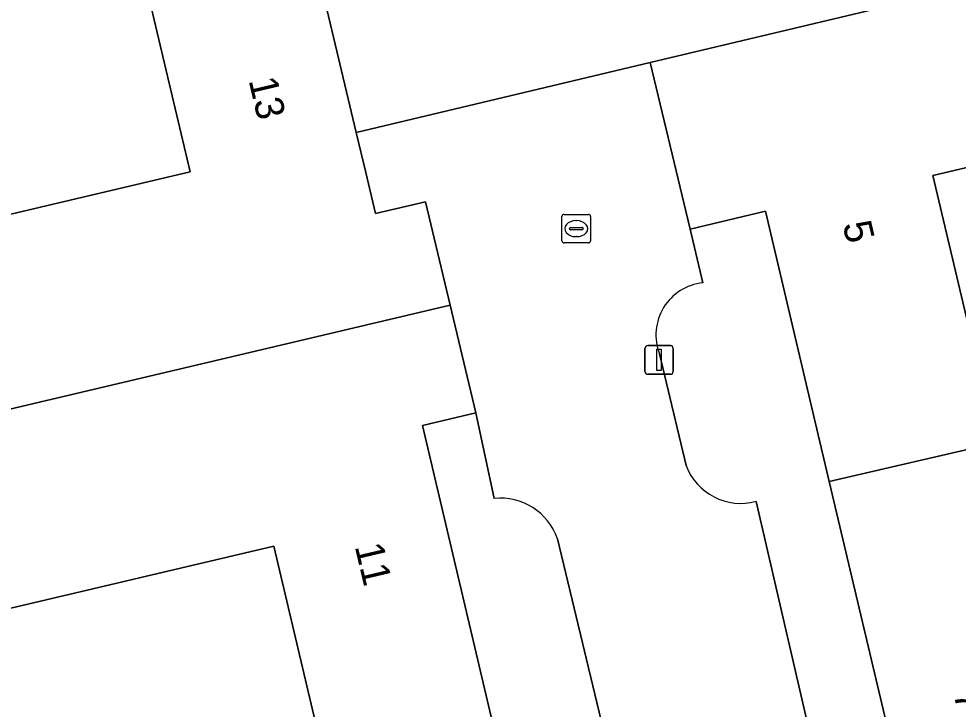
# Model space of a CAD drawing. Extents: x 157648 to 158502, y 379212 to 380938.
# Drawn here: x 158213.02 to 158245.9, y 380685.18 to 380709.33 of the extents above; entities that cross this region are included whole.
import ezdxf

# ---------------------------------------------------------------- set-up
doc = ezdxf.new("R2010")
doc.units = 0
for name, color, linetype in [('IMGEO_Erf', 7, 'Continuous'), ('IMGEO_Kolk', 7, 'Continuous'), ('IMGEO_Lichtmast', 7, 'Continuous'), ('IMGEO_Pand', 7, 'Continuous'), ('IMGEO_Pand_nummerreeks', 7, 'Continuous'), ('IMGEO_Rijbaan_lokaal_open', 7, 'Continuous')]:
    doc.layers.add(name, color=color, linetype=linetype)

msp = doc.modelspace()

# ---------------------------------------------------------------- linework, layer by layer
at = {"layer": 'IMGEO_Erf'}
for points in [[(158209.575, 380701.752), (158219.022, 380703.984), (158216.716, 380713.746)], [(158249.683, 380704.952), (158245.021, 380703.851), (158247.232, 380694.492)], [(158239.156, 380702.602), (158236.518, 380701.972), (158236.969, 380700.096)], [(158238.83, 380692.449), (158241.085, 380682.714), (158243.707, 380683.344), (158241.391, 380693.142), (158239.156, 380702.602)], [(158235.45, 380697.611), (158236.379, 380693.706)], [(158229.662, 380692.552), (158229.02, 380695.546), (158227.152, 380695.101), (158230.143, 380682.441), (158233.768, 380683.28), (158231.88, 380691.143)]]:
    msp.add_lwpolyline(points, dxfattribs=at)
msp.add_lwpolyline([(158212.334, 380688.613), (158202.676, 380686.331), (158204.989, 380676.546), (158216.449, 380679.193), (158224.26, 380681.102), (158221.948, 380690.885)], close=True, dxfattribs=at)
for centre, radius, start, end in [((158237.154, 380698.276), 1.829, 95.7962, 201.3316), ((158238.294, 380694.423), 2.045, 200.5122, 285.1856), ((158229.871, 380690.431), 2.131, 19.5142, 95.6337)]:
    msp.add_arc(centre, radius, start, end, dxfattribs=at)
at = {"layer": 'IMGEO_Kolk'}
for p, q in [((158232.036, 380701.565), (158232.036, 380702.417)), ((158232.111, 380702.491), (158232.963, 380702.491)), ((158232.524, 380702.271), (158232.549, 380702.271)), ((158233.037, 380702.417), (158233.037, 380701.565)), ((158232.295, 380701.985), (158232.295, 380701.997)), ((158232.733, 380701.948), (158232.335, 380701.948)), ((158232.338, 380702.034), (158232.736, 380702.034)), ((158232.779, 380701.997), (158232.779, 380701.985)), ((158232.547, 380701.711), (158232.522, 380701.711)), ((158232.963, 380701.491), (158232.111, 380701.491))]:
    msp.add_line(p, q, dxfattribs=at)
for points in [[(158232.036, 380701.565), (158232.036, 380702.417)], [(158232.111, 380702.491), (158232.963, 380702.491)], [(158233.037, 380702.417), (158233.037, 380701.565)], [(158232.963, 380701.491), (158232.111, 380701.491)]]:
    msp.add_lwpolyline(points, dxfattribs=at)
for centre, radius, start, end in [((158232.113, 380702.415), 0.0765, 91.552, 178.448), ((158232.113, 380702.415), 0.0765, 91.552, 178.448), ((158232.961, 380702.415), 0.0765, 1.552, 88.448), ((158232.961, 380702.415), 0.0765, 1.552, 88.448), ((158232.335, 380701.994), 0.0403, 85.8775, 175.7526), ((158232.332, 380701.984), 0.0366, 178.938, 274.7102), ((158232.736, 380701.991), 0.043, 264.8664, 352.4533), ((158232.74, 380701.996), 0.0386, 1.7309, 96.639), ((158232.113, 380701.567), 0.0765, 181.552, 268.448), ((158232.113, 380701.567), 0.0765, 181.552, 268.448), ((158232.961, 380701.567), 0.0765, 271.552, 358.448), ((158232.961, 380701.567), 0.0765, 271.552, 358.448)]:
    msp.add_arc(centre, radius, start, end, dxfattribs=at)
for centre, major_axis, ratio, start_param, end_param in [((158232.523, 380701.991), (-0.387, 0.002), 0.722429, 4.712389, 7.853982), ((158232.548, 380701.991), (-0.39, 0.002), 0.717154, 1.570796, 4.712389)]:
    msp.add_ellipse(centre, major_axis=major_axis, ratio=ratio, start_param=start_param, end_param=end_param, dxfattribs=at)
at = {"layer": 'IMGEO_Lichtmast'}
for p, q in [((158234.939, 380696.997), (158234.939, 380697.797)), ((158234.939, 380697.797), (158234.939, 380696.997)), ((158235.039, 380697.897), (158235.829, 380697.897)), ((158235.829, 380697.897), (158235.039, 380697.897)), ((158235.929, 380697.797), (158235.929, 380696.997)), ((158235.929, 380696.997), (158235.929, 380697.797)), ((158235.829, 380696.897), (158235.039, 380696.897)), ((158235.039, 380696.897), (158235.829, 380696.897))]:
    msp.add_line(p, q, dxfattribs=at)
msp.add_lwpolyline([(158235.359, 380697.772), (158235.509, 380697.772), (158235.509, 380697.022), (158235.359, 380697.022), (158235.359, 380697.772)], dxfattribs=at)
for centre, start, end in [((158235.039, 380697.797), 90, 180), ((158235.039, 380697.797), 90, 180), ((158235.829, 380697.797), 0, 90), ((158235.829, 380697.797), 360, 90), ((158235.039, 380696.997), 180, 270), ((158235.039, 380696.997), 180, 270), ((158235.829, 380696.997), 270, 0), ((158235.829, 380696.997), 270, 0)]:
    msp.add_arc(centre, 0.1, start, end, dxfattribs=at)
at = {"layer": 'IMGEO_Pand'}
for points in [[(158225.171, 380703.95), (158224.836, 380705.355), (158222.507, 380715.126), (158216.716, 380713.746), (158219.022, 380703.984), (158209.575, 380701.752), (158209.427, 380702.378), (158209.098, 380702.3), (158210.773, 380695.217), (158228.123, 380699.319), (158227.263, 380702.935), (158225.513, 380702.518)], [(158245.021, 380703.851), (158249.683, 380704.952), (158254.589, 380706.162), (158253.97, 380708.886), (158253.235, 380712.117), (158248.892, 380711.083), (158235.125, 380707.805), (158236.518, 380701.972), (158239.156, 380702.602), (158241.391, 380693.142), (158247.232, 380694.492)], [(158212.334, 380688.613), (158221.948, 380690.885), (158224.26, 380681.102), (158230.143, 380682.441), (158227.152, 380695.101), (158229.02, 380695.546), (158228.123, 380699.319), (158210.773, 380695.217)], [(158241.391, 380693.142), (158243.707, 380683.344), (158241.085, 380682.714), (158242.491, 380676.861), (158260.571, 380681.12), (158260.316, 380682.206), (158259.173, 380687.033), (158249.533, 380684.755), (158247.232, 380694.492)]]:
    msp.add_lwpolyline(points, close=True, dxfattribs=at)
at = {"layer": 'IMGEO_Rijbaan_lokaal_open'}
for points in [[(158230.481, 380727.87), (158223.363, 380726.13), (158219.966, 380725.316), (158221.618, 380718.692), (158222.507, 380715.126), (158224.836, 380705.355), (158235.125, 380707.805), (158248.892, 380711.083), (158247.603, 380716.527)], [(158236.969, 380700.096), (158236.518, 380701.972), (158235.125, 380707.805), (158224.836, 380705.355), (158225.171, 380703.95), (158225.513, 380702.518), (158227.263, 380702.935), (158228.123, 380699.319), (158229.02, 380695.546), (158229.662, 380692.552)], [(158236.379, 380693.706), (158235.45, 380697.611)], [(158241.255, 380664.317), (158244.961, 380666.536), (158242.491, 380676.861), (158241.085, 380682.714), (158238.83, 380692.449)], [(158231.88, 380691.143), (158233.768, 380683.28), (158234.625, 380679.584), (158235.558, 380676.153), (158237.572, 380675.57), (158239.207, 380668.315)]]:
    msp.add_lwpolyline(points, dxfattribs=at)
for centre, radius, start, end in [((158237.154, 380698.276), 1.829, 95.7962, 201.3316), ((158238.294, 380694.423), 2.045, 200.5122, 285.1856), ((158229.871, 380690.431), 2.131, 19.5142, 95.6337)]:
    msp.add_arc(centre, radius, start, end, dxfattribs=at)

# ---------------------------------------------------------------- texts
at = {"layer": 'IMGEO_Pand_nummerreeks'}
for s, rotation, p in [('13', 283.2981, (158221.064, 380707.183)), ('5', 283.2924, (158241.854, 380702.143)), ('11', 283.2933, (158224.779, 380690.877)), ('7', 283.2948, (158245.732, 380685.732))]:
    msp.add_text(s, height=1, rotation=rotation, dxfattribs=at).set_placement(p)

doc.saveas('drawing.dxf')
